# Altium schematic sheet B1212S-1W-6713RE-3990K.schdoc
size 277 x 190 mm; Device: default297x210; Symbol: default297x210; Name: default297x210; Date: 2026.03.17; Rev: V1.0; Size: "A4"; Id: /; File: B1212S-1W-6713RE-3990K; Sheet: /
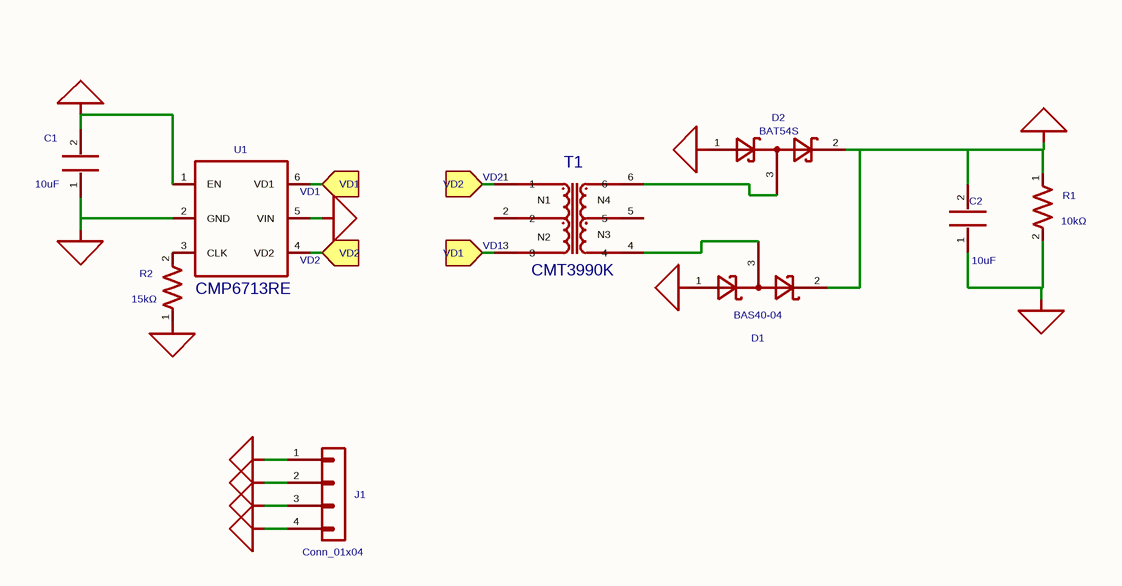
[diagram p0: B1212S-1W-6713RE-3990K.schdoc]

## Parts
C1  10uF  [MYLibrary:C0603]
C2  10uF  [MYLibrary:C0603]
D1  value BAS40-04  [MYLibrary:SOT-23]  (hidden comment: Diode_BAS40-04)
D2  value BAT54S  [MYLibrary:SOT-23]  (hidden comment: Diode_BAS40-04)
J1  value Conn_01x04  [coileasy:PinHeader_01x04_P2.54mm_Vertical]  (hidden comment: PZ2.54-1*4-WZ)
R1  10kΩ  [MYLibrary:R0603]
R2  15kΩ  [MYLibrary:R0603]
T1  CMT3990K  [CMT3990K-1]
U1  CMP6713RE  [Package_TO_SOT_SMD:SOT-23-6]

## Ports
VD1 (in), VD2 (in)

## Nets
0V: C2.1 D1.1 D2.1 J1.3(Pin_3) R1.2
+VO: C2.2 D1.2 D2.2 J1.4(Pin_4) R1.1
GND: C1.1 J1.1(Pin_1) R2.1 U1.2(GND)
VIN: C1.2 J1.2(Pin_2) U1.1(EN) U1.5(VIN)
VD1: T1.3 U1.6(VD1) ; port VD1
VD2: T1.1 U1.4(VD2) ; port VD2
NetD1_3: D1.3 T1.4
NetD2_3: D2.3 T1.6
NetR2_2: R2.2 U1.3(CLK)

Not connected (* = marked no-connect by the designer): T1 2 5

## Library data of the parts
C1 = 0805X106K250NT: 容值:10uF;精度:±10%;额定电压:25V;温度系数:X5R;; Manufacturer: FH(风华); Symbol: My_Library_C; Add into BOM: yes; 3D Model: 1ba041120af144c991958decab20d241; 3D Model Transform: 78.74,51.181,0,0,0,0,0,0.0005,0; Tolerance: ±10%; Voltage Rating: 25V; Temperature Coefficient: X5R; ki_keywords: cap capacitor; ki_fp_filters: C_*; UniqueId: 5fb4f22ffcb6a001; ModelName: C0805_L2.0-W1.3-H1.3
C2 = 0805X106K250NT: 容值:10uF;精度:±10%;额定电压:25V;温度系数:X5R;; Manufacturer: FH(风华); Symbol: My_Library_C; Add into BOM: yes; 3D Model: 1ba041120af144c991958decab20d241; 3D Model Transform: 78.74,51.181,0,0,0,0,0,0.0005,0; Tolerance: ±10%; Voltage Rating: 25V; Temperature Coefficient: X5R; ki_keywords: cap capacitor; ki_fp_filters: C_*; UniqueId: 21d50210554cb61f; ModelName: C0805_L2.0-W1.3-H1.3
D1 = Diode_BAS40-04: 40V 0.2A Dual Small Signal Schottky Diodes; ki_keywords: Schottky, Diode; ki_fp_filters: SOT?23*; Origin Footprint: Package_TO_SOT_SMD:SOT-23; UniqueId: 07a0d5848cd81316; AddInBom: yes
D2 = Diode_BAS40-04: 40V 0.2A Dual Small Signal Schottky Diodes; ki_keywords: Schottky, Diode; ki_fp_filters: SOT?23*; Origin Footprint: Package_TO_SOT_SMD:SOT-23; UniqueId: fa5cd661465da5bc; AddInBom: yes
J1 = PZ2.54-1*4-WZ: 插针结构:1x4P;间距:2.54mm;圆针/方针:方针;安装方式:弯插;排数:单排;总PIN位数:4P;额定电流:2.5A;配合针长度:3mm;塑高:2.54mm;触头材质:黄铜;触头镀层:金;工作温度:-40℃~+105℃;; Manufacturer: ZHOURI(洲日); Symbol: Connector_Generic_Conn_01x04; Add into BOM: yes; 3D Model: 408ecda0649a4165b7455247b1571d2a; 3D Model Transform: 394.4874,344.0938,0,0,0,0,0,-121.89,-118.11; Pin Structure: 1x4P; Pitch: 2.54mm; Circluar Pins/Square Pins: 方针; Current Rating: 2.5A; ki_keywords: connector; ki_fp_filters: Connector*:*_1x??_*; UniqueId: 9f49826860c2c79d; ModelName: HDR-TH_4P-P2.54-H-M-W7.7-P
R1 = RC0603FR-0710KL: 电阻类型:厚膜电阻;阻值:10kΩ;精度:±1%;功率:100mW;最大工作电压:75V;温度系数:±100ppm/℃;; Manufacturer: YAGEO(国巨); Symbol: My_Library_R; Add into BOM: yes; 3D Model: fc143cca1e79419f9cd78b61e9279f08; 3D Model Transform: 31.8897,63.7794,0,90,0,0,0,0,0; Tolerance: ±1%; Power(Watts): 100mW; Overload Voltage (Max): 75V; ki_keywords: R res resistor; ki_fp_filters: R_*; UniqueId: 4e166b190d4de1c3; ModelName: R0603
R2 = RC0603FR-0715KL: 电阻类型:厚膜电阻;阻值:15kΩ;精度:±1%;功率:100mW;工作电压:75V;温度系数:±100ppm/℃;; Manufacturer: YAGEO(国巨); Symbol: My_Library_R; Add into BOM: yes; 3D Model: fc143cca1e79419f9cd78b61e9279f08; 3D Model Transform: 31.8897,63.7794,0,90,0,0,0,0,0; Tolerance: ±1%; Power(Watts): 100mW; Voltage-Supply(Max): 75V; ki_keywords: R res resistor; ki_fp_filters: R_*; UniqueId: 06442d24ab060343; ModelName: R0603
T1 = CMT3990K-: AddInBom: yes
U1 = CMP6713RE: CMP6713RE 是全桥式变压器驱动器，芯片内部集成两个 N 型功率 MOSFET 和两个 P 型功率MOSFET，通过内部振荡器提供具有精准时序和死区时间的互补驱动信号。驱动器搭配配套的变压器，可以实现输入电压 6.5V-30V, 输出功率不超过2W 的隔离电源。采用不同的变压器，外围只需搭配简单的输入输出滤波电容，隔离变压器和整流电路，即可获得多种电压的非稳压输出。产品提供电阻选频功能，可以在 200-420 kHz 范围内连续调整开关频率，并且同时实现抖频。; Manufacturer: coileasy(线易); Symbol: MYLibrary_CMP6713RE; Add into BOM: yes; 3D Model: d6dbdad16bb04244b459daa2bbec6597; 3D Model Transform: 114.173,110.236,0,0,0,0,0,0,0; Input Voltage: 6.5V~30V; Current - Continuous Drain(Id): 300mA; Quiescent Current: 1.7mA; UniqueId: 48a4a086d8c42a18; ModelName: SOT-23-6_L2.9-W1.6-P0.95-LS2.8-BL-2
